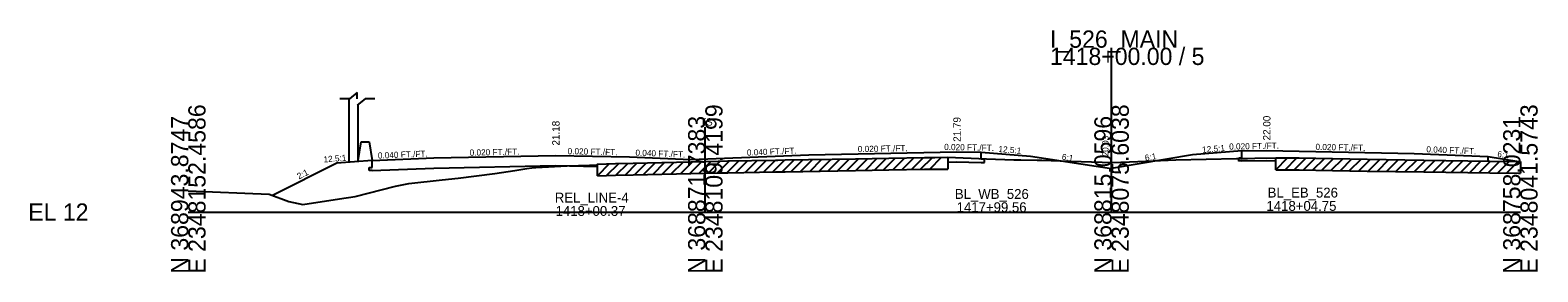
# Model space of a CAD drawing. Extents: x -170 to 2527928, y -10 to 1619750.
# Drawn here: x 3974.3 to 4219.3, y -9.7 to 29.5 of the extents above; entities that cross this region are included whole.
import ezdxf

# ---------------------------------------------------------------- set-up
doc = ezdxf.new("R2010")
doc.units = 0
for name, color, linetype in [('Default', 7, 'Continuous'), ('RD_GPK_XS_Cell', 7, 'Continuous'), ('RD_PD_NOISE-WALL-GM', 7, 'Continuous'), ('RD_XS_Base', 7, 'Continuous'), ('RD_XS_EarthShd', 7, 'Continuous'), ('RD_XS_ExGround', 7, 'Continuous'), ('RD_XS_ExPaveRet', 7, 'Continuous'), ('RD_XS_MatchLine', 7, 'Continuous'), ('RD_XS_Pave', 7, 'Continuous'), ('RD_XS_PaveShd', 7, 'Continuous'), ('RD_XS_TieSlope', 7, 'Continuous'), ('RD_XS_TX_Elev_EX', 7, 'Continuous'), ('RD_XS_TX_Slope', 7, 'Continuous'), ('RD_XS_TX_Station', 7, 'Continuous')]:
    doc.layers.add(name, color=color, linetype=linetype)

msp = doc.modelspace()

# ---------------------------------------------------------------- linework, layer by layer
at = {"layer": 'Default'}
for p, q in [((4026.21, 18.4), (4024.62, 18.4)), ((4027.46, 19.43), (4026.21, 18.4)), ((4027.46, 18.4), (4027.46, 19.43)), ((4028.71, 18.4), (4027.46, 17.37)), ((4030.3, 18.4), (4028.71, 18.4))]:
    msp.add_line(p, q, dxfattribs=at)
at = {"layer": 'RD_GPK_XS_Cell'}
for p, q in [((4150, 0), (4150, 26.67)), ((4000, 0), (4084, 0)), ((4084, 0), (4150, 0)), ((4150, 0), (4216.42, 0))]:
    msp.add_line(p, q, dxfattribs=at)
at = {"layer": 'RD_PD_NOISE-WALL-GM'}
for p, q in [((4026.08, 18.4), (4026.08, 8.08)), ((4027.58, 8.2), (4027.58, 17.47)), ((4027.58, 8.38), (4028.06, 11.38)), ((4028.06, 11.38), (4029.4, 11.38)), ((4029.4, 11.38), (4029.88, 8.38))]:
    msp.add_line(p, q, dxfattribs=at)
at = {"layer": 'RD_XS_Base'}
for p, q in [((4171.17, 8.79), (4171.17, 9.92)), ((4029.88, 7.25), (4029.88, 8.38)), ((4039.88, 7.15), (4059.67, 7.54)), ((4059.67, 7.54), (4066.47, 7.41)), ((4123.41, 8.12), (4124.83, 8.15)), ((4124.83, 8.15), (4128.83, 8.07)), ((4128.83, 8.57), (4128.83, 9.71)), ((4129.33, 8.56), (4128.83, 8.57)), ((4128.83, 8.07), (4129.33, 8.06)), ((4129.33, 8.06), (4129.33, 8.56)), ((4170.67, 8.78), (4171.17, 8.79)), ((4170.67, 8.28), (4170.67, 8.78)), ((4171.17, 8.29), (4170.67, 8.28)), ((4171.17, 8.29), (4175.17, 8.37)), ((4175.17, 8.37), (4176.68, 8.34)), ((4211.17, 8.28), (4211.17, 9.04)), ((4029.38, 7.23), (4029.88, 7.25)), ((4029.38, 6.73), (4029.38, 7.23)), ((4029.88, 6.75), (4029.38, 6.73)), ((4029.88, 6.75), (4039.88, 7.15))]:
    msp.add_line(p, q, dxfattribs=at)
at = {"layer": 'RD_XS_EarthShd'}
for p, q in [((4171.17, 9.92), (4163.17, 9.28)), ((4024.12, 7.92), (4013.68, 2.7)), ((4029.88, 8.38), (4024.12, 7.92)), ((4128.83, 9.71), (4136.83, 9.07))]:
    msp.add_line(p, q, dxfattribs=at)
at = {"layer": 'RD_XS_ExGround'}
msp.add_lwpolyline([(4000, 3.46), (4013.14, 2.9), (4016.36, 1.71), (4018.59, 1.23), (4024.59, 2.13), (4027.12, 2.51), (4033.68, 4.22), (4035.85, 4.64), (4041.22, 5.22), (4043.82, 5.5), (4049.78, 6.27), (4053.05, 6.75), (4055, 7.06), (4055.83, 7.16), (4056.49, 7.21), (4061.58, 7.5), (4065.2, 7.62), (4066.39, 7.69), (4066.47, 7.8), (4069.39, 7.88), (4072.28, 7.96), (4084, 8.22), (4086.07, 8.27), (4087.68, 8.31), (4095.38, 8.44), (4095.78, 8.44), (4096.97, 8.46), (4108.38, 8.66), (4113.83, 8.77), (4119.59, 8.88), (4121.3, 8.88), (4123.41, 8.89), (4129.66, 8.65), (4134.13, 8.5), (4135.24, 8.48), (4137.89, 8.44), (4138.67, 8.42), (4141.63, 8.33), (4150.15, 8.03), (4154.27, 8.23), (4160.45, 8.5), (4170.32, 8.71), (4172.07, 8.71), (4173.29, 8.75), (4176.68, 8.78), (4178.62, 8.78), (4180.48, 8.79), (4185.89, 8.69), (4191.55, 8.58), (4200.73, 8.43), (4204.31, 8.37), (4211.47, 8.27), (4216.14, 8.21), (4216.42, 8.2)], dxfattribs=at)
at = {"layer": 'RD_XS_ExPaveRet'}
for p, q in [((4066.47, 5.88), (4068.44, 7.86)), ((4066.47, 5.88), (4066.47, 7.8)), ((4067.97, 5.93), (4069.94, 7.9)), ((4069.47, 5.97), (4071.44, 7.94)), ((4070.97, 6.01), (4072.93, 7.98)), ((4072.47, 6.05), (4074.43, 8.01)), ((4073.97, 6.08), (4075.93, 8.04)), ((4075.47, 6.12), (4077.43, 8.08)), ((4076.97, 6.15), (4078.93, 8.11)), ((4078.47, 6.18), (4080.43, 8.14)), ((4079.97, 6.22), (4081.93, 8.18)), ((4081.47, 6.25), (4083.43, 8.21)), ((4082.97, 6.28), (4084.93, 8.25)), ((4084.47, 6.32), (4086.43, 8.28)), ((4085.97, 6.35), (4087.93, 8.31)), ((4087.47, 6.39), (4089.42, 8.34)), ((4088.97, 6.41), (4090.92, 8.36)), ((4090.47, 6.44), (4092.42, 8.39)), ((4091.97, 6.46), (4093.92, 8.41)), ((4093.47, 6.49), (4095.42, 8.44)), ((4094.97, 6.51), (4096.92, 8.46)), ((4096.47, 6.54), (4098.42, 8.49)), ((4097.97, 6.56), (4099.92, 8.51)), ((4099.47, 6.59), (4101.42, 8.54)), ((4100.97, 6.61), (4102.92, 8.57)), ((4102.47, 6.64), (4104.42, 8.59)), ((4103.97, 6.67), (4105.92, 8.62)), ((4105.47, 6.69), (4107.42, 8.64)), ((4106.97, 6.72), (4108.92, 8.67)), ((4108.47, 6.74), (4110.42, 8.7)), ((4109.97, 6.77), (4111.92, 8.73)), ((4111.47, 6.8), (4113.42, 8.76)), ((4112.97, 6.83), (4114.92, 8.79)), ((4114.47, 6.86), (4116.42, 8.82)), ((4115.97, 6.89), (4117.92, 8.85)), ((4117.47, 6.92), (4119.42, 8.88)), ((4118.97, 6.95), (4120.9, 8.88)), ((4120.47, 6.96), (4122.39, 8.89)), ((4123.41, 8.89), (4123.41, 6.97)), ((4176.68, 6.87), (4178.6, 8.78)), ((4176.68, 6.87), (4176.68, 8.78)), ((4178.18, 6.87), (4180.1, 8.79)), ((4179.68, 6.87), (4181.58, 8.77)), ((4181.18, 6.86), (4183.07, 8.74)), ((4182.68, 6.83), (4184.57, 8.71)), ((4184.18, 6.8), (4186.07, 8.69)), ((4185.68, 6.78), (4187.56, 8.66)), ((4187.18, 6.75), (4189.06, 8.63)), ((4188.68, 6.72), (4190.56, 8.6)), ((4190.18, 6.69), (4192.06, 8.57)), ((4191.68, 6.66), (4193.57, 8.55)), ((4193.18, 6.64), (4195.07, 8.52)), ((4194.68, 6.61), (4196.57, 8.5)), ((4196.18, 6.59), (4198.07, 8.47)), ((4197.68, 6.56), (4199.57, 8.45)), ((4199.18, 6.54), (4201.07, 8.42)), ((4200.68, 6.51), (4202.57, 8.4)), ((4202.18, 6.49), (4204.07, 8.37)), ((4203.68, 6.46), (4205.57, 8.35)), ((4205.18, 6.44), (4207.07, 8.33)), ((4206.68, 6.42), (4208.57, 8.31)), ((4208.18, 6.4), (4210.07, 8.29)), ((4209.68, 6.38), (4211.57, 8.27)), ((4211.18, 6.36), (4213.07, 8.25)), ((4212.68, 6.34), (4214.57, 8.23)), ((4214.18, 6.32), (4216.07, 8.21)), ((4216.42, 8.2), (4216.42, 6.29)), ((4066.47, 5.88), (4069.39, 5.97)), ((4069.39, 5.97), (4072.28, 6.05)), ((4072.28, 6.05), (4084, 6.31)), ((4084, 6.31), (4086.07, 6.35)), ((4086.07, 6.35), (4087.68, 6.39)), ((4087.68, 6.39), (4095.38, 6.52)), ((4095.38, 6.52), (4095.78, 6.52)), ((4095.78, 6.52), (4096.97, 6.55)), ((4096.97, 6.55), (4108.38, 6.74)), ((4108.38, 6.74), (4113.83, 6.85)), ((4113.83, 6.85), (4119.59, 6.96)), ((4119.59, 6.96), (4121.3, 6.96)), ((4121.3, 6.96), (4123.41, 6.97)), ((4176.68, 6.87), (4178.62, 6.87)), ((4178.62, 6.87), (4180.48, 6.87)), ((4180.48, 6.87), (4185.89, 6.77)), ((4185.89, 6.77), (4191.55, 6.66)), ((4191.55, 6.66), (4200.73, 6.51)), ((4200.73, 6.51), (4204.31, 6.45)), ((4204.31, 6.45), (4211.47, 6.35)), ((4211.47, 6.35), (4216.14, 6.29)), ((4216.14, 6.29), (4216.42, 6.29))]:
    msp.add_line(p, q, dxfattribs=at)
at = {"layer": 'RD_XS_MatchLine'}
msp.add_line((4084, 0), (4084, 13.78), dxfattribs=at)
at = {"layer": 'RD_XS_Pave'}
for p, q in [((4175.17, 10), (4199.17, 9.52)), ((4039.88, 8.78), (4059.67, 9.18)), ((4059.67, 9.18), (4071.67, 8.94)), ((4100.83, 9.31), (4124.83, 9.79))]:
    msp.add_line(p, q, dxfattribs=at)
at = {"layer": 'RD_XS_PaveShd'}
for p, q in [((4171.17, 9.92), (4175.17, 10)), ((4029.88, 8.38), (4039.88, 8.78)), ((4071.67, 8.94), (4081.66, 8.54)), ((4081.66, 8.54), (4100.83, 9.31)), ((4124.83, 9.79), (4128.83, 9.71)), ((4199.17, 9.52), (4211.17, 9.04))]:
    msp.add_line(p, q, dxfattribs=at)
at = {"layer": 'RD_XS_TieSlope'}
for p, q in [((4136.83, 9.07), (4150, 7.09)), ((4163.17, 9.28), (4150, 7.09)), ((4211.17, 9.04), (4216.19, 8.21))]:
    msp.add_line(p, q, dxfattribs=at)

# ---------------------------------------------------------------- texts
at = {"layer": 'RD_GPK_XS_Cell'}
for s, p in [('I_526_MAIN', (4140, 26.67)), ('1418+00.00 / 5', (4140, 23.87)), ('EL 12', (3974, -1.4))]:
    msp.add_text(s, height=2.8, dxfattribs=at).set_placement(p)
for s, p in [('E 2348152.4586', (4002.8, -10)), ('E 2348109.4199', (4086.8, -10)), ('E 2348075.6038', (4152.8, -10)), ('E 2348041.5743', (4219.22, -10)), ('N 368943.8747', (4000, -10)), ('N 368871.7383', (4084, -10)), ('N 368815.0596', (4150, -10)), ('N 368758.0231', (4216.42, -10))]:
    msp.add_text(s, height=2.8, rotation=90, dxfattribs=at).set_placement(p)
at = {"layer": 'RD_XS_MatchLine'}
msp.add_text('TS', height=1.2, dxfattribs=at).set_placement((4083.14, 14.03))
at = {"layer": 'RD_XS_TX_Elev_EX'}
msp.add_text('20.03', height=1, rotation=90, dxfattribs=at).set_placement((4149.5, 9.03))
at = {"layer": 'RD_XS_TX_Slope'}
for s, rotation, p in [('0.040 FT./FT.', 2.2906, (4030.82, 8.67)), ('0.020 FT./FT.', 1.1458, (4045.72, 9.15)), ('0.020 FT./FT.', 358.8542, (4061.62, 9.39)), ('0.040 FT./FT.', 357.7094, (4072.63, 9.15)), ('0.040 FT./FT.', 2.2906, (4090.77, 9.15)), ('0.020 FT./FT.', 1.1458, (4108.78, 9.72)), ('0.020 FT./FT.', 358.8542, (4122.79, 10.08)), ('12.5:1', 355.4261, (4131.59, 9.75)), ('12.5:1', 4.5739, (4164.75, 9.62)), ('0.020 FT./FT.', 1.1458, (4169.11, 10.13)), ('0.020 FT./FT.', 358.8542, (4183.12, 10.09)), ('0.040 FT./FT.', 357.7094, (4201.13, 9.7)), ('6:1', 352.6182, (4212.63, 8.96)), ('12.5:1', 4.5739, (4022.01, 8.04)), ('6:1', 350.5377, (4141.86, 8.51)), ('6:1', 9.4623, (4155.5, 8.29)), ('2:1', 26.5651, (4017.97, 5.29))]:
    msp.add_text(s, height=1, rotation=rotation, dxfattribs=at).set_placement(p)
at = {"layer": 'RD_XS_TX_Station'}
for s, p in [(' 21.18', (4060.32, 10.35)), (' 21.79', (4125.49, 10.96)), (' 22.00', (4175.82, 11.18))]:
    msp.add_text(s, height=1.2, rotation=90, dxfattribs=at).set_placement(p)
for s, p in [('REL_LINE-4', (4059.54, 1.55)), ('BL_WB_526', (4124.54, 2.14)), ('BL_EB_526', (4175.36, 2.36)), ('1418+00.37', (4059.67, -0.62)), ('1417+99.56', (4124.83, -0.01)), ('1418+04.75', (4175.17, 0.2))]:
    msp.add_text(s, height=1.6, dxfattribs=at).set_placement(p)

doc.saveas('drawing.dxf')
